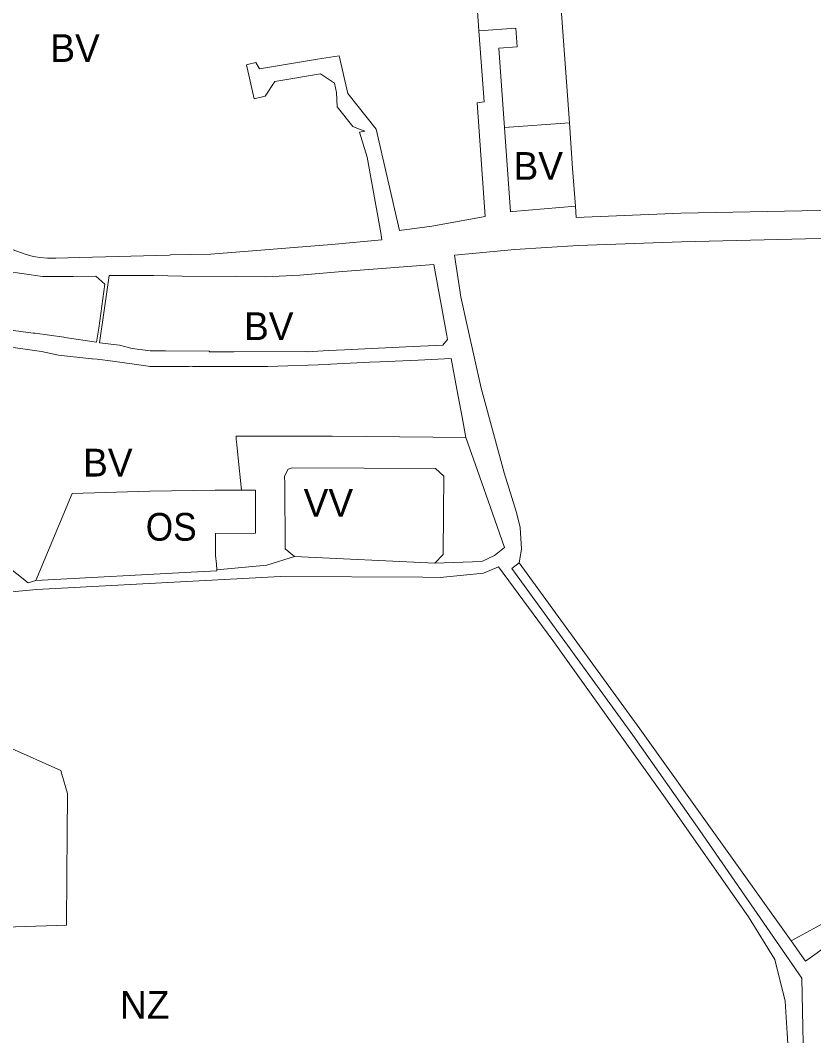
# Model space of a CAD drawing. Extents: x -650451 to -642268, y -1075216 to -1066610.
# Drawn here: x -643659.8 to -643316.5, y -1070322.5 to -1069883.3 of the extents above; entities that cross this region are included whole.
import ezdxf

# ---------------------------------------------------------------- set-up
doc = ezdxf.new("R2010")
doc.units = 0
doc.header["$LTSCALE"] = 4.8
for name, color, linetype, lineweight in [('15', 7, 'Continuous', 13), ('3', 7, 'Continuous', 13), ('36', 7, 'Continuous', 13), ('45', 7, 'Continuous', 13), ('46', 7, 'Continuous', 13), ('9', 7, 'Continuous', 13)]:
    doc.layers.add(name, color=color, linetype=linetype, lineweight=lineweight)
doc.layers.add('62', color=7, linetype='Continuous')

msp = doc.modelspace()

# ---------------------------------------------------------------- linework, layer by layer
at = {"layer": '15'}
for points in [[(-643419.62, -1069963.66), (-643419.27, -1069968.58), (-643373.94, -1069966.68), (-643254.27, -1069964.45), (-643208.32, -1069959.24), (-643177.66, -1069954.76), (-643165.1, -1069952.97), (-643104.67, -1069937.61), (-643100.67, -1069936.63), (-642920.18, -1069878.46), (-642864.62, -1069858.27), (-642788.08, -1069827.14), (-642782.69, -1069824.93), (-642703.57, -1069792.88)], [(-643663.25, -1069982.43), (-643657.61, -1069984.47), (-643654.19, -1069985.42), (-643653.13, -1069985.58), (-643651.29, -1069985.85), (-643647.93, -1069986.17), (-643644.43, -1069986.23), (-643633.99, -1069985.92), (-643595.41, -1069984.8), (-643594.61, -1069984.78), (-643577.28, -1069984.45), (-643525.19, -1069980.24), (-643503.28, -1069978.23), (-643503.83, -1069975.21), (-643509.76, -1069942.51), (-643513.03, -1069931.61), (-643510.73, -1069931.27), (-643513.45, -1069930.21), (-643515.9, -1069929.25), (-643522.73, -1069920.68), (-643522.93, -1069914.51), (-643523.88, -1069910.46), (-643529.84, -1069906.47), (-643549.62, -1069909.73), (-643553.88, -1069916.1), (-643558.02, -1069917.07), (-643558.51, -1069917.18), (-643560.27, -1069909.62), (-643561.93, -1069902.54), (-643561.44, -1069902.43), (-643557.79, -1069901.58), (-643556.34, -1069904.25), (-643531.12, -1069900.1), (-643521.85, -1069898.57), (-643518.04, -1069914.93), (-643505.75, -1069930.32), (-643495.77, -1069974.18), (-643481.78, -1069972.39), (-643458.57, -1069968.17), (-643462.1, -1069918.97), (-643459.13, -1069918.47), (-643461.326, -1069887.84)], [(-643461.326, -1069887.84), (-643445.37, -1069886.7), (-643444.79, -1069894.68), (-643452.77, -1069895.25), (-643451.74, -1069909.63), (-643450.3, -1069929.7)], [(-643450.3, -1069929.7), (-643447.67, -1069966.19), (-643446.63, -1069966), (-643419.62, -1069963.66)], [(-643254.4, -1069976.15), (-643373.64, -1069979.08), (-643418.4, -1069980.62), (-643445.77, -1069982.42), (-643471.94, -1069984.91), (-643469.13, -1070002.85), (-643466.37, -1070015.26), (-643460.33, -1070042.34), (-643455.53, -1070060.39), (-643452.9, -1070069.97), (-643450.4, -1070079.05), (-643445.02, -1070096.17), (-643443.49, -1070102.74), (-643442.9, -1070112.05), (-643443.97, -1070117.9)], [(-643466.98, -1070063.76), (-643468.6, -1070054.97), (-643470.85, -1070042.79), (-643473.29, -1070029.61), (-643487.6, -1070030.24), (-643504.24, -1070030.98), (-643508.47, -1070031.16), (-643525.54, -1070032), (-643526.62, -1070032.13), (-643552.69, -1070032.99), (-643557.2, -1070033.03), (-643565.21, -1070033.03), (-643566.24, -1070033.01), (-643577.5, -1070033.02), (-643585.22, -1070033.01), (-643586.11, -1070032.93), (-643586.7, -1070033.07), (-643603.71, -1070033.01), (-643604.4, -1070032.91), (-643619.67, -1070030.77), (-643626.45, -1070029.9), (-643628.59, -1070029.68), (-643628.86, -1070029.65), (-643643.23, -1070028.19), (-643650.61, -1070026.47), (-643657.69, -1070025.5), (-643664.03, -1070024.6)], [(-643480.35, -1070118.12), (-643460.12, -1070117.42), (-643454.6, -1070114.84), (-643450.34, -1070111.28), (-643455.5, -1070096.53), (-643461.99, -1070078.02), (-643466.98, -1070063.76)], [(-643691.59, -1070098.73), (-643656.38, -1070126.56), (-643652.98, -1070125.53)], [(-643574.72, -1070120.95), (-643553.16, -1070118.97), (-643541.19, -1070115.27), (-643480.35, -1070118.12)], [(-643443.97, -1070117.9), (-643447.11, -1070120.36), (-643394.72, -1070192.46), (-643365.81, -1070233.74), (-643321.63, -1070297.65), (-643319.68, -1070396.52), (-643323.32, -1070398.24), (-643323.48, -1070404.29)], [(-643377.4, -1070373.91), (-643369.96, -1070370.47), (-643364.57, -1070372.2), (-643339.86, -1070385.67), (-643332.76, -1070386.69), (-643328.7, -1070384.53), (-643327.21, -1070380.37), (-643328.23, -1070357.18), (-643328.02, -1070343.62), (-643327.74, -1070325.85), (-643328, -1070321.45), (-643328.87, -1070307.62), (-643333.3, -1070289.47), (-643344.72, -1070271.05), (-643381.54, -1070218.57), (-643429.35, -1070151.61), (-643452.86, -1070119.74), (-643459.33, -1070122.38), (-643478.13, -1070124.25), (-643485.57, -1070124.21), (-643547.12, -1070123.91), (-643652.76, -1070129.53), (-643669.62, -1070131.03)], [(-643652.98, -1070125.53), (-643583.12, -1070121.82), (-643574.68, -1070121.37), (-643574.72, -1070120.95)]]:
    msp.add_lwpolyline(points, dxfattribs=at)
for points in [[(-643627.08, -1069993.9), (-643636.93, -1069994.15), (-643650.19, -1069994.07), (-643665.96, -1069991.85), (-643665.68, -1069990.13), (-643676.8, -1069987.7), (-643676.97, -1069990.13), (-643686.03, -1069989.68), (-643687.34, -1070011.84), (-643678.6, -1070012.22), (-643678.79, -1070015.26), (-643654.13, -1070018.6), (-643653.27, -1070018.62), (-643640.91, -1070020.39), (-643640.48, -1070020.46), (-643626.74, -1070022.51), (-643625.81, -1070016.37), (-643623.18, -1069997.44)], [(-643589.72, -1069993.89), (-643602.06, -1069993.73), (-643621.3, -1069993.73), (-643623.65, -1070009.86), (-643625.49, -1070022.79), (-643616.85, -1070023.86), (-643611.3, -1070025.3), (-643603.53, -1070026.3), (-643596.99, -1070026.28), (-643577.93, -1070026.44), (-643577.99, -1070026.67), (-643567.42, -1070026.64), (-643536.38, -1070026.56), (-643535.64, -1070026.62), (-643526.37, -1070026.15), (-643519.5, -1070025.83), (-643493.01, -1070024.55), (-643476.97, -1070023.77), (-643474.87, -1070021.37), (-643475.19, -1070019.64), (-643480.89, -1069988.97), (-643522.05, -1069992.11), (-643538.8, -1069993.45), (-643553.73, -1069994.27), (-643566.66, -1069994.13)]]:
    msp.add_lwpolyline(points, close=True, dxfattribs=at)
at = {"layer": '3'}
msp.add_line((-643450.3, -1069929.7), (-643422.204, -1069927.68), dxfattribs=at)
for points in [[(-643463.51, -1069857.44), (-643463.31, -1069860.18), (-643461.326, -1069887.84)], [(-643461.326, -1069887.84), (-643459.13, -1069918.47), (-643462.1, -1069918.97), (-643458.57, -1069968.17), (-643481.78, -1069972.39), (-643495.77, -1069974.18), (-643505.75, -1069930.32), (-643518.04, -1069914.93), (-643521.85, -1069898.57), (-643531.12, -1069900.1), (-643556.34, -1069904.25), (-643557.79, -1069901.58), (-643561.44, -1069902.43), (-643561.93, -1069902.54), (-643560.27, -1069909.62), (-643558.51, -1069917.18), (-643558.02, -1069917.07), (-643553.88, -1069916.1), (-643549.62, -1069909.73), (-643529.84, -1069906.47), (-643523.88, -1069910.46), (-643522.93, -1069914.51), (-643522.73, -1069920.68), (-643515.9, -1069929.25), (-643513.45, -1069930.21), (-643510.73, -1069931.27), (-643513.03, -1069931.61), (-643509.76, -1069942.51), (-643503.83, -1069975.21), (-643503.28, -1069978.23), (-643525.19, -1069980.24), (-643577.28, -1069984.45), (-643594.61, -1069984.78), (-643595.41, -1069984.8), (-643633.99, -1069985.92), (-643644.43, -1069986.23), (-643647.93, -1069986.17), (-643651.29, -1069985.85), (-643653.13, -1069985.58), (-643654.19, -1069985.42), (-643657.61, -1069984.47), (-643663.25, -1069982.43)], [(-643422.204, -1069927.68), (-643420.79, -1069947.35), (-643419.62, -1069963.66)], [(-643419.62, -1069963.66), (-643446.63, -1069966), (-643447.67, -1069966.19), (-643450.3, -1069929.7)], [(-643664.03, -1070024.6), (-643657.69, -1070025.5), (-643650.61, -1070026.47), (-643643.23, -1070028.19), (-643628.86, -1070029.65), (-643628.59, -1070029.68), (-643626.45, -1070029.9), (-643619.67, -1070030.77), (-643604.4, -1070032.91), (-643603.71, -1070033.01), (-643586.7, -1070033.07), (-643586.11, -1070032.93), (-643585.22, -1070033.01), (-643577.5, -1070033.02), (-643566.24, -1070033.01), (-643565.21, -1070033.03), (-643557.2, -1070033.03), (-643552.69, -1070032.99), (-643526.62, -1070032.13), (-643525.54, -1070032), (-643508.47, -1070031.16), (-643504.24, -1070030.98), (-643487.6, -1070030.24), (-643473.29, -1070029.61), (-643470.85, -1070042.79), (-643468.6, -1070054.97), (-643466.98, -1070063.76)], [(-643466.98, -1070063.76), (-643509.99, -1070063.32), (-643524.89, -1070063.17), (-643552.04, -1070063.13), (-643566.34, -1070063.1), (-643566.34, -1070064.44), (-643566.09, -1070066.76), (-643565.62, -1070071.18), (-643564, -1070086.45)], [(-643564, -1070086.45), (-643573.77, -1070086.55), (-643575.48, -1070086.52), (-643603.66, -1070086.95), (-643637.32, -1070087.9), (-643652.98, -1070125.53)], [(-643652.98, -1070125.53), (-643656.38, -1070126.56), (-643691.59, -1070098.73)]]:
    msp.add_lwpolyline(points, dxfattribs=at)
for points in [[(-643627.08, -1069993.9), (-643623.18, -1069997.44), (-643625.81, -1070016.37), (-643626.74, -1070022.51), (-643640.48, -1070020.46), (-643640.91, -1070020.39), (-643653.27, -1070018.62), (-643654.13, -1070018.6), (-643678.79, -1070015.26), (-643678.6, -1070012.22), (-643687.34, -1070011.84), (-643686.03, -1069989.68), (-643676.97, -1069990.13), (-643676.8, -1069987.7), (-643665.68, -1069990.13), (-643665.96, -1069991.85), (-643650.19, -1069994.07), (-643636.93, -1069994.15)], [(-643589.72, -1069993.89), (-643566.66, -1069994.13), (-643553.73, -1069994.27), (-643538.8, -1069993.45), (-643522.05, -1069992.11), (-643480.89, -1069988.97), (-643475.19, -1070019.64), (-643474.87, -1070021.37), (-643476.97, -1070023.77), (-643493.01, -1070024.55), (-643519.5, -1070025.83), (-643526.37, -1070026.15), (-643535.64, -1070026.62), (-643536.38, -1070026.56), (-643567.42, -1070026.64), (-643577.99, -1070026.67), (-643577.93, -1070026.44), (-643596.99, -1070026.28), (-643603.53, -1070026.3), (-643611.3, -1070025.3), (-643616.85, -1070023.86), (-643625.49, -1070022.79), (-643623.65, -1070009.86), (-643621.3, -1069993.73), (-643602.06, -1069993.73)]]:
    msp.add_lwpolyline(points, close=True, dxfattribs=at)
at = {"layer": '36'}
msp.add_lwpolyline([(-643668.79, -1070144.14), (-643666.41, -1070182.7), (-643664.83, -1070197.66), (-643642.28, -1070207.75), (-643641.8, -1070209.42), (-643639.36, -1070217.78), (-643639.49, -1070235.43), (-643639.63, -1070253.09), (-643639.79, -1070274.68), (-643661.89, -1070275.34), (-643702.24, -1070277.22), (-643767.92, -1070278.79), (-643811.51, -1070279.84)], dxfattribs=at)
at = {"layer": '45'}
msp.add_lwpolyline([(-643541.19, -1070115.27), (-643545.17, -1070111.83), (-643545.37, -1070083.6), (-643545.39, -1070080.47), (-643543.81, -1070077.47), (-643542.2, -1070076.82), (-643480.07, -1070077.11), (-643476.46, -1070080.46), (-643476.65, -1070096.06), (-643476.86, -1070114.3), (-643480.35, -1070118.12)], close=True, dxfattribs=at)
for points in [[(-643323.48, -1070404.29), (-643323.32, -1070398.24), (-643319.68, -1070396.52), (-643321.63, -1070297.65), (-643365.81, -1070233.74), (-643394.72, -1070192.46), (-643447.11, -1070120.36), (-643443.97, -1070117.9)], [(-643443.97, -1070117.9), (-643391.77, -1070189.72), (-643326.26, -1070281.43)], [(-643326.26, -1070281.43), (-643320, -1070290.2), (-643267.75, -1070252.77), (-643208.09, -1070223.14), (-643196.16, -1070217.22), (-643185.16, -1070214.62), (-643086.36, -1070210.57), (-642946.24, -1070204.83), (-642945.59, -1070211.49)]]:
    msp.add_lwpolyline(points, dxfattribs=at)
at = {"layer": '46'}
for points in [[(-642782.69, -1069824.93), (-642788.08, -1069827.14), (-642864.62, -1069858.27), (-642920.18, -1069878.46), (-643100.67, -1069936.63), (-643104.67, -1069937.61), (-643165.1, -1069952.97), (-643177.66, -1069954.76), (-643208.32, -1069959.24), (-643254.27, -1069964.45), (-643373.94, -1069966.68), (-643419.27, -1069968.58), (-643419.62, -1069963.66)], [(-643422.204, -1069927.68), (-643427.6, -1069852.59), (-643463.51, -1069857.44)], [(-643419.62, -1069963.66), (-643420.79, -1069947.35), (-643422.204, -1069927.68)], [(-643443.97, -1070117.9), (-643442.9, -1070112.05), (-643443.49, -1070102.74), (-643445.02, -1070096.17), (-643450.4, -1070079.05), (-643452.9, -1070069.97), (-643455.53, -1070060.39), (-643460.33, -1070042.34), (-643466.37, -1070015.26), (-643469.13, -1070002.85), (-643471.94, -1069984.91), (-643445.77, -1069982.42), (-643418.4, -1069980.62), (-643373.64, -1069979.08), (-643254.4, -1069976.15)], [(-643564, -1070086.45), (-643565.62, -1070071.18), (-643566.09, -1070066.76), (-643566.34, -1070064.44), (-643566.34, -1070063.1), (-643552.04, -1070063.13), (-643524.89, -1070063.17), (-643509.99, -1070063.32), (-643466.98, -1070063.76)], [(-643466.98, -1070063.76), (-643461.99, -1070078.02), (-643455.5, -1070096.53), (-643450.34, -1070111.28), (-643454.6, -1070114.84), (-643460.12, -1070117.42), (-643480.35, -1070118.12)], [(-643480.35, -1070118.12), (-643476.86, -1070114.3), (-643476.65, -1070096.06), (-643476.46, -1070080.46), (-643480.07, -1070077.11), (-643542.2, -1070076.82), (-643543.81, -1070077.47), (-643545.39, -1070080.47), (-643545.37, -1070083.6), (-643545.17, -1070111.83), (-643541.19, -1070115.27)], [(-643574.72, -1070120.95), (-643574.92, -1070118.6), (-643575.25, -1070114.83), (-643575.33, -1070105.28), (-643558.05, -1070105.19), (-643558.02, -1070086.58), (-643564, -1070086.45)], [(-643541.19, -1070115.27), (-643553.16, -1070118.97), (-643574.72, -1070120.95)], [(-643326.26, -1070281.43), (-643391.77, -1070189.72), (-643443.97, -1070117.9)], [(-643669.62, -1070131.03), (-643652.76, -1070129.53), (-643547.12, -1070123.91), (-643485.57, -1070124.21), (-643478.13, -1070124.25), (-643459.33, -1070122.38), (-643452.86, -1070119.74), (-643429.35, -1070151.61), (-643381.54, -1070218.57), (-643344.72, -1070271.05), (-643333.3, -1070289.47), (-643328.87, -1070307.62), (-643328, -1070321.45), (-643327.74, -1070325.85), (-643328.02, -1070343.62), (-643328.23, -1070357.18), (-643327.21, -1070380.37), (-643328.7, -1070384.53), (-643332.76, -1070386.69), (-643339.86, -1070385.67), (-643364.57, -1070372.2), (-643369.96, -1070370.47), (-643377.4, -1070373.91)], [(-643811.51, -1070279.84), (-643767.92, -1070278.79), (-643702.24, -1070277.22), (-643661.89, -1070275.34), (-643639.79, -1070274.68), (-643639.63, -1070253.09), (-643639.49, -1070235.43), (-643639.36, -1070217.78), (-643641.8, -1070209.42), (-643642.28, -1070207.75), (-643664.83, -1070197.66), (-643666.41, -1070182.7), (-643668.79, -1070144.14)], [(-642950.42, -1070197.58), (-643066.26, -1070201.69), (-643187.06, -1070205.98), (-643207.1, -1070209.72), (-643219.4, -1070225.8), (-643267.55, -1070249.49), (-643326.26, -1070281.43)]]:
    msp.add_lwpolyline(points, dxfattribs=at)
at = {"layer": '9'}
for points in [[(-643652.98, -1070125.53), (-643637.32, -1070087.9), (-643603.66, -1070086.95), (-643575.48, -1070086.52), (-643573.77, -1070086.55), (-643564, -1070086.45)], [(-643564, -1070086.45), (-643558.02, -1070086.58), (-643558.05, -1070105.19), (-643575.33, -1070105.28), (-643575.25, -1070114.83), (-643574.92, -1070118.6), (-643574.72, -1070120.95)], [(-643574.72, -1070120.95), (-643574.68, -1070121.37), (-643583.12, -1070121.82), (-643652.98, -1070125.53)]]:
    msp.add_lwpolyline(points, dxfattribs=at)

# ---------------------------------------------------------------- texts
at = {"layer": '62'}
for s, p in [('BV', (-643646.768, -1069901.279)), ('BV', (-643446.375, -1069952.273)), ('BV', (-643562.957, -1070021.574)), ('BV', (-643632.582, -1070080.609)), ('VV', (-643537.177, -1070098.011)), ('NZ', (-643616.638, -1070315.152))]:
    msp.add_text(s, height=12, dxfattribs=at).set_placement(p)
at = {"layer": '62', "width": 0.95}
msp.add_text('OS', height=12, dxfattribs=at).set_placement((-643605.479, -1070108.378))

doc.saveas('drawing.dxf')
